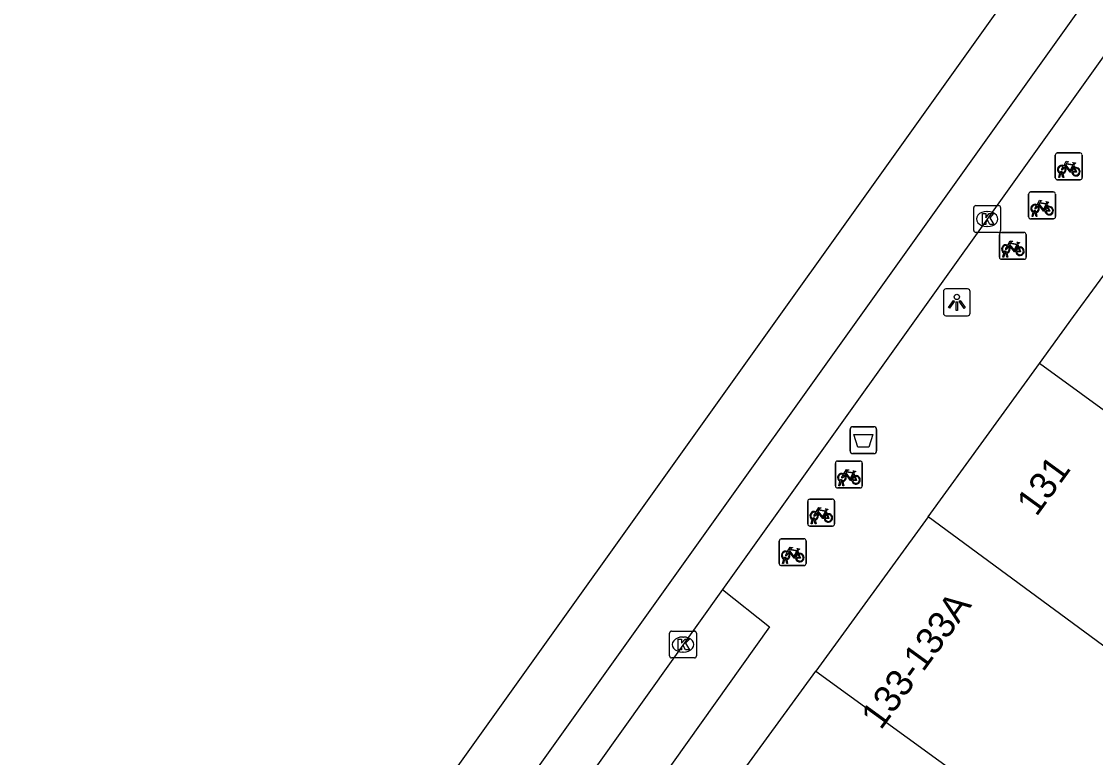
# Model space of a CAD drawing. Extents: x 160356 to 161355, y 381727 to 382845.
# Drawn here: x 160688.51 to 160728.52, y 382483.56 to 382511 of the extents above; entities that cross this region are included whole.
import ezdxf

# ---------------------------------------------------------------- set-up
doc = ezdxf.new("R2010")
doc.units = 0
for name, color, linetype in [('IMGEO_Afvalbak', 7, 'Continuous'), ('IMGEO_Fietsenrek', 7, 'Continuous'), ('IMGEO_Kolk', 7, 'Continuous'), ('IMGEO_Lichtpunt', 7, 'Continuous'), ('IMGEO_Pand', 7, 'Continuous'), ('IMGEO_Pand_nummerreeks', 7, 'Continuous'), ('IMGEO_Rijbaan_lokaal_gesloten', 7, 'Continuous'), ('IMGEO_Voetpad_open', 7, 'Continuous')]:
    doc.layers.add(name, color=color, linetype=linetype)

msp = doc.modelspace()

# ---------------------------------------------------------------- linework, layer by layer
at = {"layer": 'IMGEO_Afvalbak'}
for p, q in [((160719.372, 382494.993), (160719.372, 382495.793)), ((160719.372, 382495.793), (160719.372, 382494.993)), ((160719.472, 382495.893), (160720.262, 382495.893)), ((160720.262, 382495.893), (160719.472, 382495.893)), ((160720.362, 382495.793), (160720.362, 382494.993)), ((160720.362, 382494.993), (160720.362, 382495.793)), ((160720.262, 382494.893), (160719.472, 382494.893)), ((160719.472, 382494.893), (160720.262, 382494.893))]:
    msp.add_line(p, q, dxfattribs=at)
msp.add_lwpolyline([(160719.515, 382495.607), (160720.219, 382495.607), (160720.07, 382495.137), (160719.664, 382495.137), (160719.515, 382495.607)], dxfattribs=at)
for centre, start, end in [((160719.472, 382495.793), 90, 180), ((160719.472, 382495.793), 90, 180), ((160720.262, 382495.793), 0, 90), ((160720.262, 382495.793), 360, 90), ((160719.472, 382494.993), 180, 270), ((160719.472, 382494.993), 180, 270), ((160720.262, 382494.993), 270, 0), ((160720.262, 382494.993), 270, 0)]:
    msp.add_arc(centre, 0.1, start, end, dxfattribs=at)
at = {"layer": 'IMGEO_Fietsenrek'}
for p, q in [((160727.019, 382505.172), (160727.019, 382506.013)), ((160727.019, 382506.013), (160727.019, 382505.172)), ((160727.094, 382506.097), (160727.935, 382506.097)), ((160727.935, 382506.097), (160727.094, 382506.097)), ((160728.019, 382506.022), (160728.019, 382505.181)), ((160728.019, 382505.181), (160728.019, 382506.022)), ((160727.706, 382505.646), (160727.742, 382505.551)), ((160727.944, 382505.097), (160727.103, 382505.097)), ((160727.103, 382505.097), (160727.944, 382505.097)), ((160727.146, 382505.181), (160727.185, 382505.341)), ((160727.18, 382505.181), (160727.146, 382505.181)), ((160727.215, 382505.329), (160727.18, 382505.181)), ((160727.257, 382505.353), (160727.256, 382505.357)), ((160727.298, 382505.181), (160727.264, 382505.323)), ((160727.288, 382505.364), (160727.289, 382505.357)), ((160727.296, 382505.327), (160727.331, 382505.181)), ((160727.331, 382505.181), (160727.298, 382505.181)), ((160726.1, 382504.643), (160726.941, 382504.643)), ((160726.941, 382504.643), (160726.1, 382504.643)), ((160726.025, 382503.718), (160726.025, 382504.559)), ((160726.025, 382504.559), (160726.025, 382503.718)), ((160726.712, 382504.192), (160726.748, 382504.097)), ((160727.025, 382504.568), (160727.025, 382503.727)), ((160727.025, 382503.727), (160727.025, 382504.568)), ((160726.152, 382503.727), (160726.191, 382503.887)), ((160726.221, 382503.875), (160726.186, 382503.727)), ((160726.263, 382503.899), (160726.262, 382503.903)), ((160726.304, 382503.727), (160726.27, 382503.869)), ((160726.294, 382503.91), (160726.295, 382503.903)), ((160726.302, 382503.873), (160726.337, 382503.727)), ((160726.95, 382503.643), (160726.109, 382503.643)), ((160726.109, 382503.643), (160726.95, 382503.643)), ((160726.186, 382503.727), (160726.152, 382503.727)), ((160726.337, 382503.727), (160726.304, 382503.727)), ((160724.935, 382502.208), (160724.935, 382503.049)), ((160724.935, 382503.049), (160724.935, 382502.208)), ((160725.01, 382503.133), (160725.851, 382503.133)), ((160725.851, 382503.133), (160725.01, 382503.133)), ((160725.935, 382503.058), (160725.935, 382502.217)), ((160725.935, 382502.217), (160725.935, 382503.058)), ((160725.622, 382502.682), (160725.658, 382502.587)), ((160725.062, 382502.217), (160725.101, 382502.377)), ((160725.096, 382502.217), (160725.062, 382502.217)), ((160725.131, 382502.365), (160725.096, 382502.217)), ((160725.173, 382502.389), (160725.172, 382502.393)), ((160725.214, 382502.217), (160725.18, 382502.359)), ((160725.204, 382502.4), (160725.205, 382502.393)), ((160725.212, 382502.363), (160725.247, 382502.217)), ((160725.247, 382502.217), (160725.214, 382502.217)), ((160725.86, 382502.133), (160725.019, 382502.133)), ((160725.019, 382502.133), (160725.86, 382502.133)), ((160718.904, 382494.611), (160719.745, 382494.611)), ((160719.745, 382494.611), (160718.904, 382494.611)), ((160718.829, 382493.686), (160718.829, 382494.527)), ((160718.829, 382494.527), (160718.829, 382493.686)), ((160719.829, 382494.536), (160719.829, 382493.695)), ((160719.829, 382493.695), (160719.829, 382494.536)), ((160718.956, 382493.695), (160718.995, 382493.855)), ((160719.025, 382493.843), (160718.99, 382493.695)), ((160719.067, 382493.867), (160719.066, 382493.871)), ((160719.108, 382493.695), (160719.074, 382493.837)), ((160719.098, 382493.878), (160719.099, 382493.871)), ((160719.106, 382493.841), (160719.141, 382493.695)), ((160719.516, 382494.16), (160719.552, 382494.065)), ((160719.754, 382493.611), (160718.913, 382493.611)), ((160718.913, 382493.611), (160719.754, 382493.611)), ((160718.99, 382493.695), (160718.956, 382493.695)), ((160719.141, 382493.695), (160719.108, 382493.695)), ((160717.796, 382492.267), (160717.796, 382493.108)), ((160717.796, 382493.108), (160717.796, 382492.267)), ((160717.871, 382493.192), (160718.712, 382493.192)), ((160718.712, 382493.192), (160717.871, 382493.192)), ((160718.796, 382493.117), (160718.796, 382492.276)), ((160718.796, 382492.276), (160718.796, 382493.117)), ((160718.483, 382492.741), (160718.519, 382492.646)), ((160718.721, 382492.192), (160717.88, 382492.192)), ((160717.88, 382492.192), (160718.721, 382492.192)), ((160717.923, 382492.276), (160717.962, 382492.436)), ((160717.957, 382492.276), (160717.923, 382492.276)), ((160717.992, 382492.424), (160717.957, 382492.276)), ((160718.034, 382492.448), (160718.033, 382492.452)), ((160718.075, 382492.276), (160718.041, 382492.418)), ((160718.065, 382492.459), (160718.066, 382492.452)), ((160718.073, 382492.422), (160718.108, 382492.276)), ((160718.108, 382492.276), (160718.075, 382492.276)), ((160716.735, 382490.789), (160716.735, 382491.63)), ((160716.735, 382491.63), (160716.735, 382490.789)), ((160716.81, 382491.714), (160717.651, 382491.714)), ((160717.651, 382491.714), (160716.81, 382491.714)), ((160717.735, 382491.639), (160717.735, 382490.798)), ((160717.735, 382490.798), (160717.735, 382491.639)), ((160717.422, 382491.263), (160717.458, 382491.168)), ((160717.66, 382490.714), (160716.819, 382490.714)), ((160716.819, 382490.714), (160717.66, 382490.714)), ((160716.862, 382490.798), (160716.901, 382490.958)), ((160716.896, 382490.798), (160716.862, 382490.798)), ((160716.931, 382490.946), (160716.896, 382490.798)), ((160716.973, 382490.97), (160716.972, 382490.974)), ((160717.014, 382490.798), (160716.98, 382490.94)), ((160717.004, 382490.981), (160717.005, 382490.974)), ((160717.012, 382490.944), (160717.047, 382490.798)), ((160717.047, 382490.798), (160717.014, 382490.798))]:
    msp.add_line(p, q, dxfattribs=at)
for points in [[(160727.353, 382505.571), (160727.301, 382505.481), (160727.261, 382505.456), (160727.262, 382505.503), (160727.317, 382505.597)], [(160727.332, 382505.623), (160727.427, 382505.787), (160727.513, 382505.773), (160727.515, 382505.764), (160727.459, 382505.753), (160727.432, 382505.708), (160727.688, 382505.667)], [(160727.628, 382505.379), (160727.578, 382505.379), (160727.387, 382505.63), (160727.368, 382505.598)], [(160727.675, 382505.642), (160727.418, 382505.683), (160727.401, 382505.654), (160727.568, 382505.434), (160727.675, 382505.642)], [(160727.723, 382505.544), (160727.693, 382505.621), (160727.584, 382505.403), (160727.627, 382505.403)], [(160727.657, 382505.403), (160727.777, 382505.402), (160727.733, 382505.516)], [(160727.753, 382505.523), (160727.808, 382505.378), (160727.658, 382505.378)], [(160727.688, 382505.667), (160727.713, 382505.716), (160727.707, 382505.72), (160727.684, 382505.724), (160727.672, 382505.731), (160727.671, 382505.734), (160727.673, 382505.739), (160727.768, 382505.724), (160727.77, 382505.714), (160727.76, 382505.701), (160727.748, 382505.695), (160727.734, 382505.701), (160727.706, 382505.646)], [(160726.338, 382504.169), (160726.433, 382504.333), (160726.519, 382504.319), (160726.521, 382504.31), (160726.465, 382504.299), (160726.438, 382504.254), (160726.694, 382504.213)], [(160726.681, 382504.188), (160726.424, 382504.229), (160726.407, 382504.2), (160726.574, 382503.98), (160726.681, 382504.188)], [(160726.694, 382504.213), (160726.719, 382504.262), (160726.713, 382504.266), (160726.69, 382504.27), (160726.678, 382504.277), (160726.677, 382504.28), (160726.679, 382504.285), (160726.774, 382504.27), (160726.776, 382504.26), (160726.766, 382504.247), (160726.754, 382504.241), (160726.74, 382504.247), (160726.712, 382504.192)], [(160726.359, 382504.117), (160726.307, 382504.027), (160726.267, 382504.002), (160726.268, 382504.049), (160726.323, 382504.143)], [(160726.634, 382503.925), (160726.584, 382503.925), (160726.393, 382504.176), (160726.374, 382504.144)], [(160726.729, 382504.09), (160726.699, 382504.167), (160726.59, 382503.949), (160726.633, 382503.949)], [(160726.663, 382503.949), (160726.783, 382503.948), (160726.739, 382504.062)], [(160726.759, 382504.069), (160726.814, 382503.924), (160726.664, 382503.924)], [(160725.269, 382502.607), (160725.217, 382502.517), (160725.177, 382502.492), (160725.178, 382502.539), (160725.233, 382502.633)], [(160725.248, 382502.659), (160725.343, 382502.823), (160725.429, 382502.809), (160725.431, 382502.8), (160725.375, 382502.789), (160725.348, 382502.744), (160725.604, 382502.703)], [(160725.544, 382502.415), (160725.494, 382502.415), (160725.303, 382502.666), (160725.284, 382502.634)], [(160725.591, 382502.678), (160725.334, 382502.719), (160725.317, 382502.69), (160725.484, 382502.47), (160725.591, 382502.678)], [(160725.639, 382502.58), (160725.609, 382502.657), (160725.5, 382502.439), (160725.543, 382502.439)], [(160725.604, 382502.703), (160725.629, 382502.752), (160725.623, 382502.756), (160725.6, 382502.76), (160725.588, 382502.767), (160725.587, 382502.77), (160725.589, 382502.775), (160725.684, 382502.76), (160725.686, 382502.75), (160725.676, 382502.737), (160725.664, 382502.731), (160725.65, 382502.737), (160725.622, 382502.682)], [(160725.573, 382502.439), (160725.693, 382502.438), (160725.649, 382502.552)], [(160725.669, 382502.559), (160725.724, 382502.414), (160725.574, 382502.414)], [(160719.142, 382494.137), (160719.237, 382494.301), (160719.323, 382494.287), (160719.325, 382494.278), (160719.269, 382494.267), (160719.242, 382494.222), (160719.498, 382494.181)], [(160719.485, 382494.156), (160719.228, 382494.197), (160719.211, 382494.168), (160719.378, 382493.948), (160719.485, 382494.156)], [(160719.498, 382494.181), (160719.523, 382494.23), (160719.517, 382494.234), (160719.494, 382494.238), (160719.482, 382494.245), (160719.481, 382494.248), (160719.483, 382494.253), (160719.578, 382494.238), (160719.58, 382494.228), (160719.57, 382494.215), (160719.558, 382494.209), (160719.544, 382494.215), (160719.516, 382494.16)], [(160719.163, 382494.085), (160719.111, 382493.995), (160719.071, 382493.97), (160719.072, 382494.017), (160719.127, 382494.111)], [(160719.438, 382493.893), (160719.388, 382493.893), (160719.197, 382494.144), (160719.178, 382494.112)], [(160719.533, 382494.058), (160719.503, 382494.135), (160719.394, 382493.917), (160719.437, 382493.917)], [(160719.467, 382493.917), (160719.587, 382493.916), (160719.543, 382494.03)], [(160719.563, 382494.037), (160719.618, 382493.892), (160719.468, 382493.892)], [(160718.13, 382492.666), (160718.078, 382492.576), (160718.038, 382492.551), (160718.039, 382492.598), (160718.094, 382492.692)], [(160718.109, 382492.718), (160718.204, 382492.882), (160718.29, 382492.868), (160718.292, 382492.859), (160718.236, 382492.848), (160718.209, 382492.803), (160718.465, 382492.762)], [(160718.405, 382492.474), (160718.355, 382492.474), (160718.164, 382492.725), (160718.145, 382492.693)], [(160718.452, 382492.737), (160718.195, 382492.778), (160718.178, 382492.749), (160718.345, 382492.529), (160718.452, 382492.737)], [(160718.5, 382492.639), (160718.47, 382492.716), (160718.361, 382492.498), (160718.404, 382492.498)], [(160718.434, 382492.498), (160718.554, 382492.497), (160718.51, 382492.611)], [(160718.53, 382492.618), (160718.585, 382492.473), (160718.435, 382492.473)], [(160718.465, 382492.762), (160718.49, 382492.811), (160718.484, 382492.815), (160718.461, 382492.819), (160718.449, 382492.826), (160718.448, 382492.829), (160718.45, 382492.834), (160718.545, 382492.819), (160718.547, 382492.809), (160718.537, 382492.796), (160718.525, 382492.79), (160718.511, 382492.796), (160718.483, 382492.741)], [(160717.048, 382491.24), (160717.143, 382491.404), (160717.229, 382491.39), (160717.231, 382491.381), (160717.175, 382491.37), (160717.148, 382491.325), (160717.404, 382491.284)], [(160717.069, 382491.188), (160717.017, 382491.098), (160716.977, 382491.073), (160716.978, 382491.12), (160717.033, 382491.214)], [(160717.344, 382490.996), (160717.294, 382490.996), (160717.103, 382491.247), (160717.084, 382491.215)], [(160717.391, 382491.259), (160717.134, 382491.3), (160717.117, 382491.271), (160717.284, 382491.051), (160717.391, 382491.259)], [(160717.439, 382491.161), (160717.409, 382491.238), (160717.3, 382491.02), (160717.343, 382491.02)], [(160717.373, 382491.02), (160717.493, 382491.019), (160717.449, 382491.133)], [(160717.469, 382491.14), (160717.524, 382490.995), (160717.374, 382490.995)], [(160717.404, 382491.284), (160717.429, 382491.333), (160717.423, 382491.337), (160717.4, 382491.341), (160717.388, 382491.348), (160717.387, 382491.351), (160717.389, 382491.356), (160717.484, 382491.341), (160717.486, 382491.331), (160717.476, 382491.318), (160717.464, 382491.312), (160717.45, 382491.318), (160717.422, 382491.263)]]:
    msp.add_lwpolyline(points, dxfattribs=at)
for centre, radius, start, end in [((160727.097, 382506.019), 0.0779, 92.4484, 184.2845), ((160727.097, 382506.019), 0.0779, 92.4484, 184.2845), ((160727.941, 382506.019), 0.0779, 2.4484, 94.2845), ((160727.941, 382506.019), 0.0779, 2.4484, 94.2845), ((160727.259, 382505.482), 0.159, 62.6766, 242.1369), ((160727.259, 382505.482), 0.129, 63.3192, 238.903), ((160727.239, 382505.353), 0.0499, 12.8025, 158.6934), ((160727.259, 382505.482), 0.129, 283.6043, 43.4302), ((160727.259, 382505.482), 0.159, 283.5766, 46.6042), ((160727.786, 382505.398), 0.159, 113.3408, 178.3217), ((160727.786, 382505.398), 0.159, 187.0065, 105.7708), ((160727.786, 382505.398), 0.129, 113.923, 177.9556), ((160727.786, 382505.398), 0.129, 188.6715, 104.5883), ((160727.097, 382505.175), 0.0779, 182.4484, 274.2845), ((160727.097, 382505.175), 0.0779, 182.4484, 274.2845), ((160727.259, 382505.482), 0.159, 253.9967, 271.7867), ((160727.239, 382505.353), 0.0174, 12.8025, 163.4502), ((160727.259, 382505.482), 0.129, 253.415, 269.0204), ((160727.941, 382505.175), 0.0779, 272.4484, 4.2845), ((160727.941, 382505.175), 0.0779, 272.4484, 4.2845), ((160726.103, 382504.565), 0.0779, 92.4484, 184.2845), ((160726.103, 382504.565), 0.0779, 92.4484, 184.2845), ((160726.947, 382504.565), 0.0779, 2.4484, 94.2845), ((160726.947, 382504.565), 0.0779, 2.4484, 94.2845), ((160726.265, 382504.028), 0.159, 62.6766, 242.1369), ((160726.265, 382504.028), 0.129, 63.3192, 238.903), ((160726.245, 382503.899), 0.0499, 12.8025, 158.6934), ((160726.265, 382504.028), 0.159, 253.9967, 271.7867), ((160726.245, 382503.899), 0.0174, 12.8025, 163.4502), ((160726.265, 382504.028), 0.129, 253.415, 269.0204), ((160726.265, 382504.028), 0.129, 283.6043, 43.4302), ((160726.265, 382504.028), 0.159, 283.5766, 46.6042), ((160726.792, 382503.944), 0.159, 113.3408, 178.3217), ((160726.792, 382503.944), 0.159, 187.0065, 105.7708), ((160726.792, 382503.944), 0.129, 113.923, 177.9556), ((160726.792, 382503.944), 0.129, 188.6715, 104.5883), ((160726.103, 382503.721), 0.0779, 182.4484, 274.2845), ((160726.103, 382503.721), 0.0779, 182.4484, 274.2845), ((160726.947, 382503.721), 0.0779, 272.4484, 4.2845), ((160726.947, 382503.721), 0.0779, 272.4484, 4.2845), ((160725.013, 382503.055), 0.0779, 92.4484, 184.2845), ((160725.013, 382503.055), 0.0779, 92.4484, 184.2845), ((160725.857, 382503.055), 0.0779, 2.4484, 94.2845), ((160725.857, 382503.055), 0.0779, 2.4484, 94.2845), ((160725.175, 382502.518), 0.159, 62.6766, 242.1369), ((160725.175, 382502.518), 0.129, 63.3192, 238.903), ((160725.175, 382502.518), 0.129, 283.6043, 43.4302), ((160725.175, 382502.518), 0.159, 283.5766, 46.6042), ((160725.702, 382502.434), 0.159, 187.0065, 105.7708), ((160725.013, 382502.211), 0.0779, 182.4484, 274.2845), ((160725.013, 382502.211), 0.0779, 182.4484, 274.2845), ((160725.155, 382502.389), 0.0499, 12.8025, 158.6934), ((160725.175, 382502.518), 0.159, 253.9967, 271.7867), ((160725.155, 382502.389), 0.0174, 12.8025, 163.4502), ((160725.175, 382502.518), 0.129, 253.415, 269.0204), ((160725.702, 382502.434), 0.159, 113.3408, 178.3217), ((160725.702, 382502.434), 0.129, 113.923, 177.9556), ((160725.702, 382502.434), 0.129, 188.6715, 104.5883), ((160725.857, 382502.211), 0.0779, 272.4484, 4.2845), ((160725.857, 382502.211), 0.0779, 272.4484, 4.2845), ((160718.907, 382494.533), 0.0779, 92.4484, 184.2845), ((160718.907, 382494.533), 0.0779, 92.4484, 184.2845), ((160719.751, 382494.533), 0.0779, 2.4484, 94.2845), ((160719.751, 382494.533), 0.0779, 2.4484, 94.2845), ((160719.069, 382493.996), 0.159, 62.6766, 242.1369), ((160719.069, 382493.996), 0.129, 63.3192, 238.903), ((160719.049, 382493.867), 0.0499, 12.8025, 158.6934), ((160719.069, 382493.996), 0.159, 253.9967, 271.7867), ((160719.049, 382493.867), 0.0174, 12.8025, 163.4502), ((160719.069, 382493.996), 0.129, 253.415, 269.0204), ((160719.069, 382493.996), 0.129, 283.6043, 43.4302), ((160719.069, 382493.996), 0.159, 283.5766, 46.6042), ((160719.596, 382493.912), 0.159, 113.3408, 178.3217), ((160719.596, 382493.912), 0.159, 187.0065, 105.7708), ((160719.596, 382493.912), 0.129, 113.923, 177.9556), ((160719.596, 382493.912), 0.129, 188.6715, 104.5883), ((160718.907, 382493.689), 0.0779, 182.4484, 274.2845), ((160718.907, 382493.689), 0.0779, 182.4484, 274.2845), ((160719.751, 382493.689), 0.0779, 272.4484, 4.2845), ((160719.751, 382493.689), 0.0779, 272.4484, 4.2845), ((160717.874, 382493.114), 0.0779, 92.4484, 184.2845), ((160717.874, 382493.114), 0.0779, 92.4484, 184.2845), ((160718.718, 382493.114), 0.0779, 2.4484, 94.2845), ((160718.718, 382493.114), 0.0779, 2.4484, 94.2845), ((160718.036, 382492.577), 0.159, 62.6766, 242.1369), ((160718.036, 382492.577), 0.129, 63.3192, 238.903), ((160718.036, 382492.577), 0.129, 283.6043, 43.4302), ((160718.036, 382492.577), 0.159, 283.5766, 46.6042), ((160718.563, 382492.493), 0.159, 113.3408, 178.3217), ((160718.563, 382492.493), 0.159, 187.0065, 105.7708), ((160718.563, 382492.493), 0.129, 113.923, 177.9556), ((160718.563, 382492.493), 0.129, 188.6715, 104.5883), ((160717.874, 382492.27), 0.0779, 182.4484, 274.2845), ((160717.874, 382492.27), 0.0779, 182.4484, 274.2845), ((160718.016, 382492.448), 0.0499, 12.8025, 158.6934), ((160718.036, 382492.577), 0.159, 253.9967, 271.7867), ((160718.016, 382492.448), 0.0174, 12.8025, 163.4502), ((160718.036, 382492.577), 0.129, 253.415, 269.0204), ((160718.718, 382492.27), 0.0779, 272.4484, 4.2845), ((160718.718, 382492.27), 0.0779, 272.4484, 4.2845), ((160716.813, 382491.636), 0.0779, 92.4484, 184.2845), ((160716.813, 382491.636), 0.0779, 92.4484, 184.2845), ((160717.657, 382491.636), 0.0779, 2.4484, 94.2845), ((160717.657, 382491.636), 0.0779, 2.4484, 94.2845), ((160716.975, 382491.099), 0.159, 62.6766, 242.1369), ((160716.975, 382491.099), 0.129, 63.3192, 238.903), ((160716.955, 382490.97), 0.0499, 12.8025, 158.6934), ((160716.955, 382490.97), 0.0174, 12.8025, 163.4502), ((160716.975, 382491.099), 0.129, 283.6043, 43.4302), ((160716.975, 382491.099), 0.159, 283.5766, 46.6042), ((160717.502, 382491.015), 0.159, 113.3408, 178.3217), ((160717.502, 382491.015), 0.159, 187.0065, 105.7708), ((160717.502, 382491.015), 0.129, 113.923, 177.9556), ((160717.502, 382491.015), 0.129, 188.6715, 104.5883), ((160716.813, 382490.792), 0.0779, 182.4484, 274.2845), ((160716.813, 382490.792), 0.0779, 182.4484, 274.2845), ((160716.975, 382491.099), 0.159, 253.9967, 271.7867), ((160716.975, 382491.099), 0.129, 253.415, 269.0204), ((160717.657, 382490.792), 0.0779, 272.4484, 4.2845), ((160717.657, 382490.792), 0.0779, 272.4484, 4.2845)]:
    msp.add_arc(centre, radius, start, end, dxfattribs=at)
at = {"layer": 'IMGEO_Kolk'}
for p, q in [((160723.982, 382503.21), (160723.982, 382504.062)), ((160724.057, 382504.136), (160724.909, 382504.136)), ((160724.47, 382503.916), (160724.495, 382503.916)), ((160724.983, 382504.062), (160724.983, 382503.21)), ((160724.909, 382503.136), (160724.057, 382503.136)), ((160724.493, 382503.356), (160724.468, 382503.356)), ((160712.65, 382487.348), (160712.65, 382488.2)), ((160712.725, 382488.274), (160713.577, 382488.274)), ((160713.651, 382488.2), (160713.651, 382487.348)), ((160713.138, 382488.054), (160713.163, 382488.054)), ((160713.161, 382487.494), (160713.136, 382487.494)), ((160713.577, 382487.274), (160712.725, 382487.274))]:
    msp.add_line(p, q, dxfattribs=at)
for points in [[(160723.982, 382503.21), (160723.982, 382504.062)], [(160724.057, 382504.136), (160724.909, 382504.136)], [(160724.303, 382503.836), (160724.426, 382503.836), (160724.426, 382503.685), (160724.556, 382503.836), (160724.72, 382503.836), (160724.574, 382503.685), (160724.727, 382503.436), (160724.575, 382503.436), (160724.49, 382503.6), (160724.426, 382503.533), (160724.426, 382503.436), (160724.303, 382503.436), (160724.303, 382503.836)], [(160724.983, 382504.062), (160724.983, 382503.21)], [(160724.909, 382503.136), (160724.057, 382503.136)], [(160712.65, 382487.348), (160712.65, 382488.2)], [(160712.725, 382488.274), (160713.577, 382488.274)], [(160713.651, 382488.2), (160713.651, 382487.348)], [(160712.971, 382487.974), (160713.094, 382487.974), (160713.094, 382487.823), (160713.224, 382487.974), (160713.388, 382487.974), (160713.242, 382487.823), (160713.395, 382487.574), (160713.243, 382487.574), (160713.158, 382487.738), (160713.094, 382487.671), (160713.094, 382487.574), (160712.971, 382487.574), (160712.971, 382487.974)], [(160713.577, 382487.274), (160712.725, 382487.274)]]:
    msp.add_lwpolyline(points, dxfattribs=at)
for centre, start, end in [((160724.059, 382504.06), 91.552, 178.448), ((160724.059, 382504.06), 91.552, 178.448), ((160724.907, 382504.06), 1.552, 88.448), ((160724.907, 382504.06), 1.552, 88.448), ((160724.059, 382503.212), 181.552, 268.448), ((160724.059, 382503.212), 181.552, 268.448), ((160724.907, 382503.212), 271.552, 358.448), ((160724.907, 382503.212), 271.552, 358.448), ((160712.727, 382488.198), 91.552, 178.448), ((160712.727, 382488.198), 91.552, 178.448), ((160713.575, 382488.198), 1.552, 88.448), ((160713.575, 382488.198), 1.552, 88.448), ((160712.727, 382487.35), 181.552, 268.448), ((160712.727, 382487.35), 181.552, 268.448), ((160713.575, 382487.35), 271.552, 358.448), ((160713.575, 382487.35), 271.552, 358.448)]:
    msp.add_arc(centre, 0.0765, start, end, dxfattribs=at)
for centre, major_axis, ratio, start_param, end_param in [((160724.469, 382503.636), (-0.387, 0.002), 0.722429, 4.712389, 7.853982), ((160724.494, 382503.636), (-0.39, 0.002), 0.717154, 1.570796, 4.712389), ((160713.137, 382487.774), (-0.387, 0.002), 0.722429, 4.712389, 7.853982), ((160713.162, 382487.774), (-0.39, 0.002), 0.717154, 1.570796, 4.712389)]:
    msp.add_ellipse(centre, major_axis=major_axis, ratio=ratio, start_param=start_param, end_param=end_param, dxfattribs=at)
at = {"layer": 'IMGEO_Lichtpunt'}
for p, q in [((160723.753, 382501.028), (160722.945, 382501.028)), ((160723.753, 382501.028), (160722.945, 382501.028)), ((160722.851, 382500.933), (160722.851, 382500.126)), ((160722.851, 382500.933), (160722.851, 382500.126)), ((160723.847, 382500.126), (160723.847, 382500.933)), ((160723.847, 382500.126), (160723.847, 382500.933)), ((160722.945, 382500.032), (160723.753, 382500.032)), ((160722.945, 382500.032), (160723.753, 382500.032))]:
    msp.add_line(p, q, dxfattribs=at)
for points in [[(160723.225, 382500.597), (160723.264, 382500.569), (160723.076, 382500.307), (160723.038, 382500.334), (160723.225, 382500.597)], [(160723.437, 382500.569), (160723.475, 382500.596), (160723.662, 382500.334), (160723.623, 382500.306), (160723.437, 382500.569)], [(160723.327, 382500.549), (160723.374, 382500.549), (160723.374, 382500.227), (160723.327, 382500.227), (160723.327, 382500.549)]]:
    msp.add_lwpolyline(points, dxfattribs=at)
msp.add_circle((160723.35, 382500.731), 0.0994, dxfattribs=at)
for centre, start, end in [((160722.945, 382500.933), 90, 180), ((160722.945, 382500.933), 90, 180), ((160723.753, 382500.933), 0, 90), ((160723.753, 382500.933), 0, 90), ((160722.945, 382500.126), 180, 270), ((160722.945, 382500.126), 180, 270), ((160723.753, 382500.126), 270, 0), ((160723.753, 382500.126), 270, 360)]:
    msp.add_arc(centre, 0.0946, start, end, dxfattribs=at)
at = {"layer": 'IMGEO_Pand'}
for points in [[(160726.425, 382498.244), (160727.701, 382500), (160729.405, 382502.344)], [(160722.278, 382492.538), (160726.425, 382498.244)], [(160741.425, 382488.937), (160738.352, 382490.489), (160734.471, 382492.397), (160726.425, 382498.244)], [(160722.278, 382492.538), (160718.092, 382486.78)], [(160729.016, 382487.572), (160722.278, 382492.538)], [(160713.556, 382480.539), (160718.092, 382486.78)], [(160718.092, 382486.78), (160724.901, 382481.832)]]:
    msp.add_lwpolyline(points, dxfattribs=at)
at = {"layer": 'IMGEO_Rijbaan_lokaal_gesloten'}
for points in [[(160690.494, 382459.018), (160691.804, 382460.856), (160741.274, 382530.158), (160766.403, 382566.076), (160767.839, 382565.099)], [(160737.875, 382529.651), (160689.911, 382462.447), (160688.505, 382460.429)], [(160729.116, 382510.121), (160714.615, 382489.823)], [(160714.615, 382489.823), (160704.295, 382475.32)]]:
    msp.add_lwpolyline(points, dxfattribs=at)
at = {"layer": 'IMGEO_Voetpad_open'}
msp.add_lwpolyline([(160714.615, 382489.823), (160716.371, 382488.433), (160706.129, 382474.035), (160704.295, 382475.32)], dxfattribs=at)

# ---------------------------------------------------------------- texts
at = {"layer": 'IMGEO_Pand_nummerreeks'}
for s, rotation, p in [('131', 53.9898, (160726.315, 382492.513)), ('133-133A', 53.9726, (160720.519, 382484.557))]:
    msp.add_text(s, height=1, rotation=rotation, dxfattribs=at).set_placement(p)

doc.saveas('drawing.dxf')
